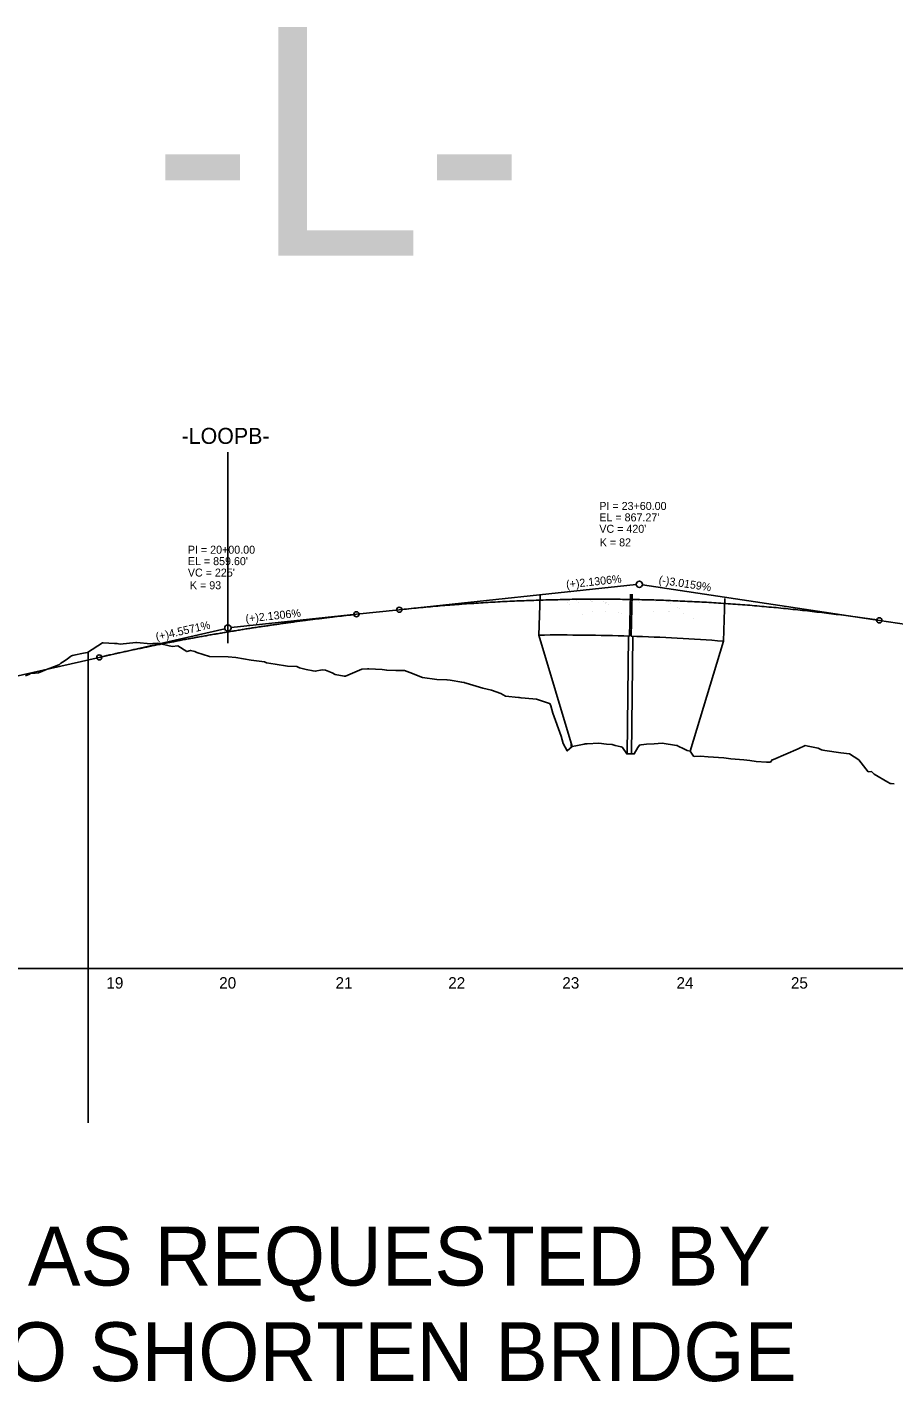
# Model space of a CAD drawing. Extents: x 570622 to 580296, y -55533 to -48575.
# Drawn here: x 574622 to 575380, y -53797 to -52612 of the extents above; entities that cross this region are included whole.
import ezdxf

# ---------------------------------------------------------------- set-up
doc = ezdxf.new("R2010")
doc.units = 0
for name, color, linetype in [('Default', 7, 'Continuous'), ('Exist Profile Cell', 7, 'Continuous'), ('Exist Vertical Profile Ground Line', 7, 'Continuous'), ('Exist Vertical Profile Horizontal Axis Label Major', 7, 'Continuous'), ('Prop Vertical Profile Curve Label', 7, 'Continuous'), ('Prop Vertical Profile Grade', 7, 'Continuous'), ('Prop Vertical Profile Grade Label', 7, 'Continuous'), ('Prop VPI Label', 7, 'Continuous')]:
    doc.layers.add(name, color=color, linetype=linetype)

msp = doc.modelspace()

# ---------------------------------------------------------------- linework, layer by layer
at = {"layer": 'Default'}
for p, q in [((574797.6, -52983.6), (574797.6, -53150.7)), ((575070.8, -53108.9), (575069.7, -53143.6)), ((575094.7, -53114.8), (575094.7, -53114.8)), ((575096.2, -53116.5), (575096.2, -53116.5)), ((575096.2, -53116.5), (575096.2, -53116.5)), ((575102.8, -53113.1), (575102.8, -53113.1)), ((575104.3, -53114.7), (575104.3, -53114.7)), ((575104.3, -53114.7), (575104.3, -53114.7)), ((575114.5, -53112.9), (575114.5, -53112.9)), ((575116, -53114.4), (575116, -53114.4)), ((575116.2, -53114.4), (575116.2, -53114.4)), ((575126.3, -53114), (575126.3, -53114)), ((575127.7, -53115.5), (575127.7, -53115.5)), ((575127.7, -53115.6), (575127.7, -53115.6)), ((575128.9, -53114.8), (575128.9, -53114.8)), ((575130.4, -53116.4), (575130.4, -53116.4)), ((575130.4, -53116.4), (575130.4, -53116.4)), ((575149.1, -53144.5), (575149.9, -53107.9)), ((575150.4, -53144.5), (575151.3, -53107.9)), ((575156.6, -53113.3), (575156.6, -53113.3)), ((575158.1, -53114.9), (575158.1, -53114.9)), ((575158.1, -53114.9), (575158.1, -53114.9)), ((575169.9, -53112.6), (575169.9, -53112.6)), ((575170.7, -53113), (575170.7, -53113)), ((575171.8, -53114.2), (575171.8, -53114.2)), ((575183.2, -53114.6), (575183.2, -53114.6)), ((575184.7, -53116.2), (575184.7, -53116.2)), ((575184.7, -53116.2), (575184.7, -53116.2)), ((575232.4, -53111.5), (575231.2, -53148.9)), ((575107.9, -53125.2), (575107.9, -53125.2)), ((575107.9, -53125.2), (575107.9, -53125.2)), ((575116.3, -53123.1), (575116.3, -53123.1)), ((575116.3, -53123.1), (575116.3, -53123.1)), ((575128, -53122.7), (575128, -53122.7)), ((575128.1, -53122.6), (575128.1, -53122.6)), ((575139.6, -53123.7), (575139.6, -53123.7)), ((575139.6, -53123.7), (575139.6, -53123.7)), ((575142.3, -53124.5), (575142.3, -53124.5)), ((575142.3, -53124.5), (575142.3, -53124.5)), ((575169.9, -53123.3), (575169.9, -53123.3)), ((575169.9, -53123.3), (575169.9, -53123.3)), ((575183.3, -53122.7), (575183.3, -53122.7)), ((575183.6, -53122.7), (575183.6, -53122.7)), ((575191, -53119.1), (575191, -53119.1)), ((575193, -53120.7), (575193, -53120.7)), ((575193, -53120.7), (575193, -53120.7)), ((575196.6, -53124.6), (575196.6, -53124.6)), ((575196.6, -53124.6), (575196.6, -53124.6)), ((575205.1, -53128.8), (575205.1, -53128.8)), ((575205.1, -53128.8), (575205.1, -53128.8)), ((575098.9, -53241.1), (575069.7, -53143.6)), ((575147, -53248.1), (575148.1, -53144.5)), ((575150.8, -53248.2), (575151.9, -53144.6)), ((575202.2, -53245.3), (575231.2, -53148.9)), ((574675.5, -53570.4), (574675.5, -53158.7)), ((575097.9, -53241.1), (575097.9, -53237.7)), ((575098.9, -53241.1), (575097.9, -53241.1))]:
    msp.add_line(p, q, dxfattribs=at)
for start, end in [(88.1608, 90.5075), (85.7299, 88.1202)]:
    msp.add_arc((575086.8, -55082), 1938.5, start, end, dxfattribs=at)
at = {"layer": 'Exist Profile Cell'}
msp.add_line((573797.6, -53435.4), (576393.8, -53435.4), dxfattribs=at)
at = {"layer": 'Exist Vertical Profile Ground Line'}
for points in [[(574620.6, -53179.3), (574623.4, -53178), (574625.4, -53177), (574626.2, -53177), (574629.1, -53176.8), (574631.9, -53176.6), (574634.7, -53175.5), (574637.5, -53174.4), (574640.3, -53173.2), (574643.1, -53172.1), (574643.6, -53171.9), (574646, -53171), (574648.8, -53169.9), (574650.2, -53169.3), (574651.6, -53168.3), (574654.4, -53166.3), (574657.2, -53164.3), (574660, -53162.3), (574660.7, -53161.8), (574661.8, -53161.4), (574662.9, -53161.2), (574665.7, -53160.6), (574668.5, -53160), (574671.3, -53159.4), (574674.7, -53158.7), (574687.8, -53150.4), (574688.4, -53150.3), (574698.3, -53151.1), (574700.6, -53150.9), (574703.5, -53151.4), (574717.2, -53150.2), (574717.6, -53150.2), (574730.3, -53151.2), (574731.9, -53151), (574736.4, -53150.8), (574748.8, -53153.5), (574753.7, -53152.9), (574761.7, -53158.1), (574765, -53157), (574768.7, -53158.1), (574770.4, -53158.9), (574781.6, -53162.3), (574797.8, -53162.6), (574804.5, -53163.2), (574817.9, -53165.5)], [(574817.9, -53165.5), (574829.6, -53167.1), (574831.4, -53167.8), (574835.2, -53168.4), (574839.1, -53169), (574849.7, -53170.7), (574858, -53171.2), (574860.2, -53172.2), (574866, -53173.7), (574872.2, -53175), (574874, -53175.2), (574880, -53174), (574883.1, -53174.3), (574889, -53176.6), (574891.6, -53178.1), (574899.4, -53179.5), (574900.4, -53179.6), (574904.6, -53177.9), (574914.8, -53173.3), (574919.9, -53173.1), (574920.9, -53173.1), (574932.5, -53173.6), (574936.6, -53174.4), (574944.6, -53174.5), (574952.2, -53174.5), (574956.7, -53176.4), (574967.8, -53180.8), (574980.4, -53182.5), (574989.3, -53182.6), (574992.1, -53183.1), (575002.3, -53184.9), (575004.3, -53185.2), (575004.9, -53185.5), (575006, -53185.8), (575020.6, -53189.9), (575028.4, -53191.8), (575036.3, -53194.8), (575040.6, -53197), (575051.9, -53198.1), (575052.5, -53198.2), (575054.2, -53198.5), (575064.5, -53199.4), (575067.6, -53199.8), (575078, -53203.2), (575079.3, -53203.5), (575080.2, -53205.5), (575082, -53211.8), (575089.1, -53231.9), (575091.1, -53238.5), (575094.5, -53245), (575098.9, -53241.1), (575102, -53240.6), (575109.4, -53238.9), (575110.3, -53238.7), (575112.1, -53238.6), (575122.1, -53238.3), (575128.8, -53238.9), (575133.7, -53239.3), (575134.8, -53239.7), (575136.4, -53240.2), (575141.8, -53241.3), (575142.7, -53241.6), (575143, -53242), (575146.6, -53247.4), (575149.1, -53247.6), (575153.1, -53247.6), (575156.4, -53242), (575157.6, -53239.9), (575159.1, -53239.6), (575163.9, -53238.9), (575170.6, -53238.6), (575177.6, -53238.3), (575190.1, -53240.2), (575190.7, -53240.3), (575191.5, -53240.7), (575196.4, -53243.1), (575198.9, -53244.3), (575199.5, -53244.6), (575202.2, -53245.3), (575204.9, -53249.5), (575206.2, -53249.8), (575211, -53249.6), (575217.8, -53250.1), (575231.4, -53250.9), (575237.6, -53251.8), (575249.1, -53252.7), (575254.3, -53253.3), (575259.9, -53254.2), (575269, -53254.7), (575272.3, -53254.8), (575273.7, -53252.7), (575274.9, -53252.5), (575296.7, -53243), (575302.6, -53240.2), (575305.3, -53240.9), (575314.2, -53242.6), (575316.9, -53244), (575318.3, -53244.3), (575320, -53244.6), (575333.9, -53246.6), (575341.4, -53247.5)], [(575341.4, -53247.5), (575349.5, -53252.7), (575357.9, -53263.2), (575360.7, -53263), (575363.1, -53265.2), (575374.9, -53272.2), (575377, -53273.4), (575377.8, -53273.5), (575380.6, -53273.6)]]:
    msp.add_lwpolyline(points, dxfattribs=at)
at = {"layer": 'Prop Vertical Profile Curve Label'}
for centre in [(574910.1, -53125.4), (574947.6, -53121.4), (575367.6, -53130.7), (574685.1, -53163.1)]:
    msp.add_circle(centre, 2.25, dxfattribs=at)
at = {"layer": 'Prop Vertical Profile Grade'}
for p, q in [((574910.1, -53125.4), (574947.6, -53121.4)), ((575367.6, -53130.7), (575487.6, -53148.8)), ((574602.6, -53181.9), (574685.1, -53163.1))]:
    msp.add_line(p, q, dxfattribs=at)
for points in [[(574947.6, -53121.4), (574956, -53120.6), (574964.4, -53119.7), (574972.8, -53119), (574981.2, -53118.2), (574989.6, -53117.5), (574998, -53116.9), (575006.4, -53116.2), (575014.8, -53115.7), (575023.2, -53115.1), (575031.6, -53114.7), (575040, -53114.2), (575048.4, -53113.8), (575056.8, -53113.5), (575065.2, -53113.2), (575073.6, -53112.9), (575082, -53112.7), (575090.4, -53112.5), (575098.8, -53112.3), (575107.2, -53112.2), (575115.6, -53112.2), (575124, -53112.2), (575132.4, -53112.2), (575140.8, -53112.3), (575149.2, -53112.4), (575157.6, -53112.6), (575166, -53112.8), (575174.4, -53113), (575182.8, -53113.3), (575191.2, -53113.7), (575199.6, -53114.1), (575208, -53114.5), (575216.4, -53114.9), (575224.8, -53115.5), (575233.2, -53116), (575241.6, -53116.6), (575250, -53117.2), (575258.4, -53117.9), (575266.8, -53118.7), (575275.2, -53119.4), (575283.6, -53120.2), (575292, -53121.1), (575300.4, -53122), (575308.8, -53122.9), (575317.2, -53123.9), (575325.6, -53124.9), (575334, -53126), (575342.4, -53127.1), (575350.8, -53128.3), (575359.2, -53129.5), (575367.6, -53130.7)], [(574685.1, -53163.1), (574689.6, -53162), (574694.1, -53161), (574698.6, -53160), (574703.1, -53159), (574707.6, -53158.1), (574712.1, -53157.1), (574716.6, -53156.1), (574721.1, -53155.2), (574725.6, -53154.3), (574730.1, -53153.3), (574734.6, -53152.4), (574739.1, -53151.5), (574743.6, -53150.6), (574748.1, -53149.8), (574752.6, -53148.9), (574757.1, -53148), (574761.6, -53147.2), (574766.1, -53146.4), (574770.6, -53145.5), (574775.1, -53144.7), (574779.6, -53143.9), (574784.1, -53143.1), (574788.6, -53142.4), (574793.1, -53141.6), (574797.6, -53140.8), (574802.1, -53140.1), (574806.6, -53139.4), (574811.1, -53138.6), (574815.6, -53137.9), (574820.1, -53137.2), (574824.6, -53136.5), (574829.1, -53135.8), (574833.6, -53135.2), (574838.1, -53134.5), (574842.6, -53133.9), (574847.1, -53133.2), (574851.6, -53132.6), (574856.1, -53132), (574860.6, -53131.4), (574865.1, -53130.8), (574869.6, -53130.2), (574874.1, -53129.6), (574878.6, -53129.1), (574883.1, -53128.5), (574887.6, -53128), (574892.1, -53127.4), (574896.6, -53126.9), (574901.1, -53126.4), (574905.6, -53125.9), (574910.1, -53125.4)]]:
    msp.add_spline(points, degree=3, dxfattribs=at)
at = {"layer": 'Prop VPI Label'}
for p, q in [((574947.6, -53121.4), (575154.9, -53099.4)), ((575367.6, -53130.7), (575160.3, -53099.5)), ((574910.1, -53125.4), (574800.4, -53137.1)), ((574685.1, -53163.1), (574794.9, -53138))]:
    msp.add_line(p, q, dxfattribs=at)
for centre in [(575157.6, -53099.1), (574797.6, -53137.4)]:
    msp.add_circle(centre, 2.75, dxfattribs=at)

# ---------------------------------------------------------------- texts
at = {"layer": 'Default'}
for s, height, p in [('-L-', 200, (574730.9, -52811.6)), ('LOWERED THE GRADE AS REQUESTED BY ', 51.45, (573835.2, -53712.7)), ('STRUCTURE DESIGN TO SHORTEN BRIDGE', 51.45, (573835.2, -53796.3))]:
    msp.add_text(s, height=height, dxfattribs=at).set_placement(p)
at = {"layer": 'Exist Profile Cell'}
msp.add_text('-LOOPB-', height=14, dxfattribs=at).set_placement((574757.1, -52976.3))
at = {"layer": 'Exist Vertical Profile Horizontal Axis Label Major'}
for s, p in [('19', (574691.3, -53452.9)), ('20', (574790, -53452.9)), ('21', (574891.8, -53452.9)), ('22', (574990.4, -53452.9)), ('23', (575090.2, -53452.9)), ('24', (575190.1, -53452.9)), ('25', (575290.2, -53452.9))]:
    msp.add_text(s, height=10, dxfattribs=at).set_placement(p)
at = {"layer": 'Prop Vertical Profile Curve Label'}
for s, p in [("VC = 420'", (575122.6, -53054.1)), ('K = 82', (575123, -53066)), ("VC = 225'", (574762.6, -53092.4)), ('K = 93', (574764.4, -53103.5))]:
    msp.add_text(s, height=7, dxfattribs=at).set_placement(p)
at = {"layer": 'Prop Vertical Profile Grade Label'}
for s, rotation, p in [('(+)2.1306%', 6.0807, (575093.9, -53102.8)), ('(-)3.0159%', 351.4247, (575174.2, -53098.5)), ('(+)2.1306%', 6.0807, (574813.4, -53132.7)), ('(+)4.5571%', 12.8361, (574735.3, -53148.6))]:
    msp.add_text(s, height=7, rotation=rotation, dxfattribs=at).set_placement(p)
at = {"layer": 'Prop VPI Label'}
for s, p in [('PI = 23+60.00', (575122.6, -53034.1)), ("EL = 867.27'", (575122.6, -53044.1)), ('PI = 20+00.00', (574762.6, -53072.4)), ("EL = 859.60'", (574762.6, -53082.4))]:
    msp.add_text(s, height=7, dxfattribs=at).set_placement(p)

doc.saveas('drawing.dxf')
